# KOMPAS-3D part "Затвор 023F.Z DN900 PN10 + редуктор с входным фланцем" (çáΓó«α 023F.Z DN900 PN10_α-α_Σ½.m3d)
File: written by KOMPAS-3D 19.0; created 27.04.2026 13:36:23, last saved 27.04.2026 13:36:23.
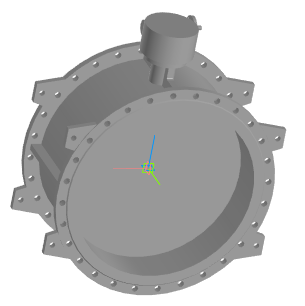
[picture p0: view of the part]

Document properties: Полное имя файла: ..\..\Затвор 023F.Z DN200-DN1600_редуктор с входным фланцем\Затвор 023F.Z DN900 PN10 + редуктор с входным фланцем.a3d

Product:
- Part/product: Затвор 023F.Z DN900 PN10 + редуктор с входным фланцем
    Масса: 949.197

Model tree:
1. Операция без истории:1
